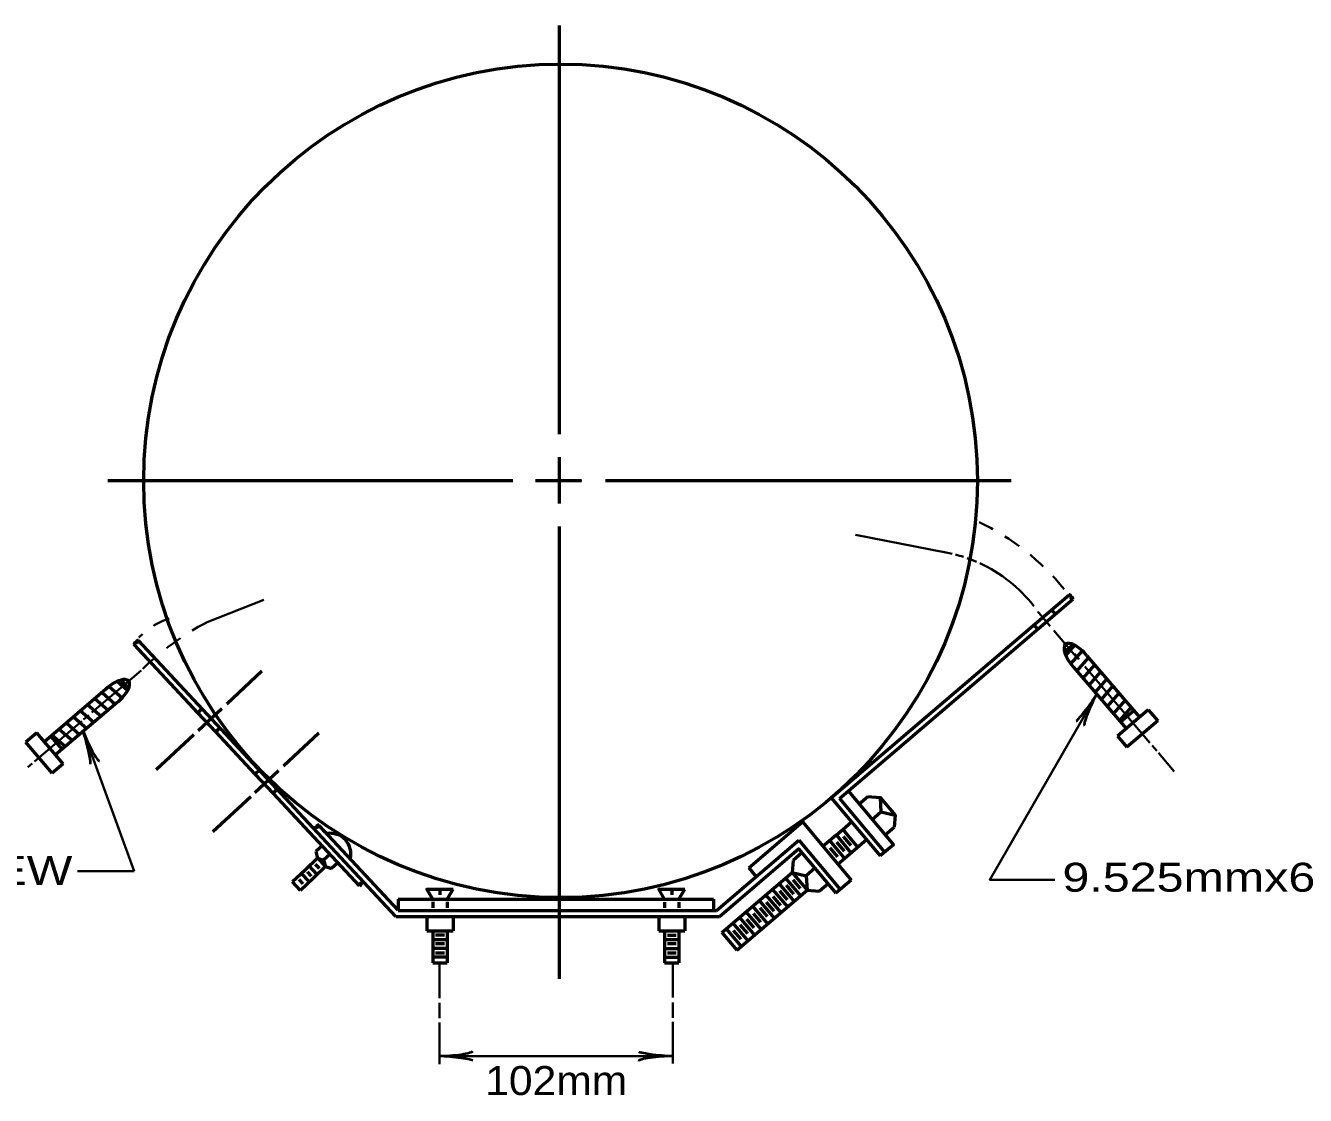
# Model space of a CAD drawing. Extents: x 14808 to 15663, y 10944 to 11488.
# Drawn here: x 15031.3 to 15163.9, y 11082.5 to 11193.4 of the extents above; entities that cross this region are included whole.
import ezdxf

# ---------------------------------------------------------------- set-up
doc = ezdxf.new("R2010")
doc.units = 0
doc.header["$LTSCALE"] = 1.2
doc.linetypes.add('SHORT_DASHED', pattern=[2.7, 1.5, -1.2])
doc.layers.add('1', color=7, linetype='Continuous', lineweight=53)

msp = doc.modelspace()

# ---------------------------------------------------------------- linework, layer by layer
at = {"layer": '1'}
for p, q in [((15086.651, 11151.055), (15086.651, 11193.393)), ((15086.651, 11146.233), (15086.651, 11148.668)), ((15039.851, 11146.233), (15081.805, 11146.233)), ((15084.167, 11146.233), (15088.942, 11146.233)), ((15086.651, 11143.863), (15086.651, 11146.233)), ((15091.416, 11146.233), (15133.451, 11146.233)), ((15114.819, 11113.353), (15139.457, 11134.395)), ((15115.661, 11113.283), (15139.846, 11133.939)), ((15137.632, 11132.837), (15138.021, 11132.38)), ((15135.807, 11131.278), (15136.196, 11130.822)), ((15069.706, 11101.058), (15043.022, 11129.672)), ((15049.193, 11122.175), (15042.594, 11129.251)), ((15138.992, 11128.472), (15139.9, 11129.247)), ((15139.132, 11128.093), (15140.059, 11129.16)), ((15139.65, 11127.226), (15140.834, 11128.588)), ((15139.933, 11126.908), (15145.387, 11120.523)), ((15140.286, 11126.495), (15141.48, 11127.869)), ((15140.917, 11125.757), (15142.111, 11127.131)), ((15141.312, 11128.065), (15146.756, 11121.692)), ((15041.223, 11125.557), (15041.998, 11124.65)), ((15052.168, 11123.103), (15055.819, 11126.506)), ((15141.547, 11125.019), (15142.741, 11126.392)), ((15142.178, 11124.281), (15143.372, 11125.654)), ((15039.659, 11124.616), (15033.274, 11119.162)), ((15039.246, 11124.263), (15040.62, 11123.069)), ((15039.977, 11124.899), (15041.339, 11123.715)), ((15040.844, 11125.418), (15041.911, 11124.49)), ((15142.808, 11123.543), (15144.002, 11124.916)), ((15040.816, 11123.237), (15034.443, 11117.793)), ((15037.77, 11123.002), (15039.144, 11121.808)), ((15038.508, 11123.632), (15039.882, 11122.438)), ((15143.438, 11122.805), (15144.632, 11124.178)), ((15144.069, 11122.067), (15145.263, 11123.44)), ((15036.294, 11121.741), (15037.667, 11120.547)), ((15037.032, 11122.372), (15038.405, 11121.178)), ((15049.621, 11122.595), (15049.193, 11122.175)), ((15051.035, 11120.199), (15049.193, 11122.175)), ((15049.196, 11120.331), (15051.655, 11122.624)), ((15147.668, 11122.471), (15144.474, 11119.744)), ((15144.699, 11121.328), (15145.893, 11122.702)), ((15146.171, 11122.377), (15144.802, 11121.207)), ((15147.668, 11122.471), (15148.642, 11121.331)), ((15034.818, 11120.48), (15036.191, 11119.286)), ((15035.556, 11121.111), (15036.929, 11119.917)), ((15051.463, 11120.62), (15051.035, 11120.199)), ((15148.642, 11121.331), (15145.449, 11118.603)), ((15032.495, 11120.075), (15031.354, 11119.101)), ((15034.082, 11115.907), (15031.354, 11119.101)), ((15035.222, 11116.881), (15032.495, 11120.075)), ((15035.128, 11118.378), (15033.958, 11119.747)), ((15034.079, 11119.85), (15035.453, 11118.656)), ((15044.848, 11116.277), (15048.76, 11119.925)), ((15055.128, 11115.81), (15051.035, 11120.199)), ((15058.06, 11116.666), (15061.711, 11120.07)), ((15144.474, 11119.744), (15145.449, 11118.603)), ((15035.222, 11116.881), (15034.082, 11115.907)), ((15055.088, 11113.895), (15057.546, 11116.187)), ((15055.557, 11116.23), (15055.128, 11115.81)), ((15056.97, 11113.834), (15055.128, 11115.81)), ((15057.399, 11114.255), (15056.97, 11113.835)), ((15065.918, 11104.239), (15056.97, 11113.835)), ((15050.739, 11109.841), (15054.652, 11113.489)), ((15114.819, 11113.353), (15119.878, 11107.325)), ((15115.661, 11113.283), (15120.337, 11107.711)), ((15117.689, 11112.705), (15118.602, 11113.484)), ((15119.878, 11113.391), (15121.437, 11111.566)), ((15119.067, 11111.092), (15119.965, 11111.887)), ((15062.382, 11109.791), (15061.703, 11110.519)), ((15061.707, 11110.515), (15061.707, 11110.515)), ((15069.931, 11101.696), (15061.745, 11110.474)), ((15106.258, 11106.082), (15111.833, 11110.844)), ((15115.316, 11109.494), (15116, 11110.079)), ((15116, 11110.079), (15116.913, 11110.858)), ((15116, 11110.079), (15117.543, 11108.24)), ((15120.417, 11109.511), (15121.329, 11110.291)), ((15062.068, 11108.383), (15061.404, 11107.775)), ((15102.931, 11101.663), (15111.472, 11108.958)), ((15111.472, 11108.958), (15115.749, 11103.861)), ((15113.947, 11108.325), (15115.316, 11109.495)), ((15114.632, 11108.91), (15116.174, 11107.071)), ((15115.316, 11109.495), (15116.859, 11107.656)), ((15115.364, 11108.746), (15116.143, 11107.834)), ((15115.49, 11106.487), (15118.456, 11109.02)), ((15116.048, 11109.331), (15116.827, 11108.418)), ((15061.591, 11107.104), (15060.286, 11105.865)), ((15061.591, 11107.104), (15062.417, 11106.234)), ((15062.879, 11107.499), (15062.215, 11106.891)), ((15111.78, 11107.658), (15110.853, 11106.867)), ((15114.679, 11108.161), (15115.459, 11107.249)), ((15060.286, 11105.865), (15058.98, 11104.626)), ((15060.942, 11105.231), (15060.529, 11105.666)), ((15061.554, 11105.414), (15060.728, 11106.285)), ((15061.769, 11106.024), (15061.37, 11106.443)), ((15063.689, 11106.614), (15063.026, 11106.006)), ((15106.258, 11106.082), (15107.029, 11105.163)), ((15113.13, 11106.049), (15112.217, 11105.27)), ((15115.49, 11106.487), (15116.89, 11104.818)), ((15059.806, 11103.756), (15058.98, 11104.626)), ((15060.098, 11104.438), (15059.669, 11104.89)), ((15060.741, 11104.643), (15059.915, 11105.513)), ((15109.402, 11104.444), (15110.961, 11102.619)), ((15110.087, 11105.028), (15111.645, 11103.203)), ((15110.771, 11105.613), (15112.33, 11103.788)), ((15110.819, 11104.864), (15111.597, 11103.952)), ((15114.48, 11104.44), (15113.581, 11103.673)), ((15116.89, 11104.818), (15115.289, 11103.475)), ((15074.27, 11103.897), (15074.27, 11103.297)), ((15075.02, 11102.858), (15075.62, 11103.897)), ((15098.282, 11103.884), (15098.282, 11103.284)), ((15099.032, 11102.845), (15099.632, 11103.884)), ((15105.03, 11097.553), (15112.33, 11103.788)), ((15108.034, 11103.275), (15109.592, 11101.45)), ((15108.718, 11103.859), (15110.277, 11102.034)), ((15108.765, 11103.111), (15109.544, 11102.199)), ((15109.45, 11103.695), (15110.229, 11102.783)), ((15110.134, 11104.28), (15110.913, 11103.368)), ((15069.92, 11102.858), (15102.62, 11102.858)), ((15069.92, 11102.858), (15069.92, 11101.658)), ((15073.52, 11102.558), (15073.52, 11101.958)), ((15075.02, 11102.558), (15075.02, 11101.958)), ((15097.532, 11102.545), (15097.532, 11101.945)), ((15099.032, 11102.545), (15099.032, 11101.945)), ((15102.62, 11102.858), (15102.62, 11101.658)), ((15106.665, 11102.106), (15108.223, 11100.281)), ((15107.349, 11102.69), (15108.908, 11100.865)), ((15107.397, 11101.942), (15108.176, 11101.03)), ((15108.081, 11102.526), (15108.86, 11101.614)), ((15069.706, 11101.058), (15103.22, 11101.058)), ((15069.92, 11101.658), (15102.92, 11101.658)), ((15072.92, 11101.058), (15072.92, 11099.558)), ((15075.62, 11101.058), (15075.62, 11099.558)), ((15096.932, 11101.045), (15096.932, 11099.545)), ((15099.632, 11101.045), (15099.632, 11099.545)), ((15105.296, 11100.937), (15106.855, 11099.112)), ((15105.98, 11101.521), (15107.539, 11099.696)), ((15106.028, 11100.773), (15106.807, 11099.861)), ((15106.712, 11101.357), (15107.491, 11100.445)), ((15072.92, 11099.558), (15075.62, 11099.558)), ((15073.52, 11099.558), (15073.52, 11096.257)), ((15073.82, 11099.14), (15074.72, 11099.14)), ((15075.02, 11099.558), (15075.02, 11096.257)), ((15096.932, 11099.545), (15099.632, 11099.545)), ((15097.532, 11099.545), (15097.532, 11096.245)), ((15097.832, 11099.128), (15098.732, 11099.128)), ((15099.032, 11099.545), (15099.032, 11096.245)), ((15103.471, 11099.378), (15105.03, 11097.553)), ((15103.927, 11099.768), (15105.486, 11097.943)), ((15103.927, 11099.768), (15105.486, 11097.943)), ((15104.612, 11100.352), (15106.17, 11098.527)), ((15104.659, 11099.604), (15105.438, 11098.692)), ((15105.344, 11100.188), (15106.123, 11099.276)), ((15073.52, 11098.67), (15075.02, 11098.67)), ((15073.52, 11097.754), (15075.02, 11097.754)), ((15073.82, 11098.249), (15074.72, 11098.249)), ((15097.532, 11098.657), (15099.032, 11098.657)), ((15097.532, 11097.741), (15099.032, 11097.741)), ((15097.832, 11098.236), (15098.732, 11098.236)), ((15073.52, 11096.858), (15075.02, 11096.858)), ((15073.82, 11097.283), (15074.72, 11097.283)), ((15097.532, 11096.845), (15099.032, 11096.845)), ((15097.832, 11097.271), (15098.732, 11097.271)), ((15073.52, 11096.257), (15075.02, 11096.257)), ((15097.532, 11096.245), (15099.032, 11096.245))]:
    msp.add_line(p, q, dxfattribs=at)
at = {"layer": '1', "lineweight": 13}
for p, q in [((15088.942, 11146.233), (15088.979, 11146.233)), ((15056.049, 11114.822), (15056.473, 11115.217))]:
    msp.add_line(p, q, dxfattribs=at)
at = {"layer": '1', "lineweight": 35}
for p, q in [((15117.344, 11140.593), (15126.692, 11138.776)), ((15126.396, 11138.833), (15127.356, 11138.647)), ((15056.022, 11133.877), (15050.16, 11131.568)), ((15136.329, 11132.514), (15137.499, 11131.145)), ((15137.884, 11130.693), (15140.382, 11127.769)), ((15140.037, 11128.27), (15140.519, 11127.725)), ((15141.076, 11126.957), (15147.841, 11119.036)), ((15038.199, 11122.185), (15043.31, 11126.55)), ((15037.344, 11121.455), (15037.89, 11121.92)), ((15032.254, 11117.107), (15037.144, 11121.284)), ((15037.304, 11120.246), (15042.58, 11105.753)), ((15148.068, 11118.77), (15148.541, 11118.216)), ((15148.728, 11117.997), (15150.358, 11116.089)), ((15031.558, 11116.513), (15032.022, 11116.909)), ((15036.716, 11105.753), (15042.58, 11105.753)), ((15074.222, 11096.251), (15074.222, 11092.587)), ((15098.383, 11096.3), (15098.383, 11092.637)), ((15074.222, 11092.092), (15074.222, 11090.508)), ((15098.383, 11092.141), (15098.383, 11090.557)), ((15074.222, 11090.062), (15074.222, 11085.751)), ((15098.383, 11090.112), (15098.383, 11085.8)), ((15074.206, 11086.583), (15098.311, 11086.583))]:
    msp.add_line(p, q, dxfattribs=at)
at = {"layer": '1'}
for points in [[(15086.651, 11094.575), (15086.651, 11103.126), (15086.651, 11141.475)], [(15116.574, 11114.062), (15121.257, 11108.482), (15119.878, 11107.325)], [(15118.602, 11113.484), (15119.878, 11113.391), (15119.965, 11111.887), (15121.437, 11111.566), (15121.329, 11110.291)], [(15111.833, 11110.844), (15113.947, 11108.325), (15115.49, 11106.487)], [(15061.404, 11107.775), (15061.591, 11107.104), (15062.215, 11106.891), (15062.417, 11106.234), (15063.026, 11106.006)], [(15103.22, 11101.058), (15111.433, 11108.072), (15115.289, 11103.475)], [(15062.417, 11106.234), (15061.112, 11104.995), (15059.806, 11103.756)], [(15110.853, 11106.867), (15110.771, 11105.613), (15112.217, 11105.27), (15112.33, 11103.788), (15113.581, 11103.673)], [(15103.471, 11099.378), (15110.087, 11105.028), (15110.771, 11105.613)], [(15073.52, 11102.858), (15072.92, 11103.897), (15075.62, 11103.897)], [(15097.532, 11102.845), (15096.932, 11103.884), (15099.632, 11103.884)]]:
    msp.add_lwpolyline(points, dxfattribs=at)
at = {"layer": '1', "lineweight": 35}
msp.add_lwpolyline([(15137.989, 11104.854), (15131.231, 11104.854), (15142.338, 11124.092)], dxfattribs=at)
at = {"layer": '1'}
msp.add_circle((15086.766, 11146.205), 43.2, dxfattribs=at)
at = {"layer": '1', "linetype": 'SHORT_DASHED', "lineweight": 35}
for centre, radius, start, end in [((15118.921, 11118.68), 25.821, 39.09076, 64.25674), ((15048.357, 11125.007), 7.247, 107.18277, 136.93055), ((15062.9, 11106.992), 27.682, 117.40174, 135.04708)]:
    msp.add_arc(centre, radius, start, end, dxfattribs=at)
at = {"layer": '1', "lineweight": 35}
for start, end in [(72.09704, 75.39826), (66.7088, 70.55356), (37.97532, 65.20978), (34.61481, 35.37094)]:
    msp.add_arc((15123.868, 11123.912), 15.141, start, end, dxfattribs=at)
at = {"layer": '1'}
for centre, radius, start, end in [((15139.486, 11134.223), 0.175, 341.35274, 99.6479), ((15139.817, 11134.111), 0.175, 161.35274, 279.6479), ((15139.681, 11133.995), 0.175, 341.35274, 99.6479), ((15042.978, 11129.503), 0.175, 75.35274, 193.6479), ((15042.852, 11129.631), 0.175, 255.35274, 13.6479), ((15042.764, 11129.293), 0.175, 75.35274, 193.6479), ((15140.131, 11128.795), 1.184, 154.26025, 195.83671), ((15142.622, 11129.591), 3.798, 197.13743, 224.94055), ((15139.401, 11128.173), 1.184, 64.26025, 105.83671), ((15137.9, 11125.423), 4.316, 37.7559, 62.16939), ((15042.342, 11121.927), 3.798, 107.13743, 134.94055), ((15041.546, 11124.418), 1.184, 64.26025, 105.83671), ((15038.174, 11126.649), 4.316, 307.7559, 332.16939), ((15040.924, 11125.148), 1.184, 334.26025, 15.83671), ((15061.436, 11110.145), 0.175, 73.35274, 191.6479), ((15061.657, 11110.347), 0.175, 73.35274, 191.6479), ((15061.536, 11110.479), 0.175, 253.35274, 11.6479), ((15061.536, 11110.479), 0.175, 11.56977, 11.63706), ((15062.89, 11107.524), 2.149, 346.12036, 99.8792), ((15066.077, 11104.312), 0.175, 86.35274, 204.6479), ((15065.929, 11104.413), 0.175, 266.35274, 24.6479), ((15066.099, 11104.661), 0.175, 266.35274, 24.6479)]:
    msp.add_arc(centre, radius, start, end, dxfattribs=at)
at = {"layer": '1', "lineweight": 40}
for centre, major_axis, ratio, start_param, end_param in [((15141.446, 11123.055), (-1.236, -1.72), 0.07063, 6.2823074, 8.5597026), ((15141.971, 11122.793), (0.909, 1.949), 0.122415, 0.8963533, 3.1415927), ((15037.526, 11118.896), (0.523, -2.053), 0.07063, 6.2823074, 8.5597026), ((15038.064, 11119.129), (-0.909, 1.95), 0.122415, 0.8963533, 3.1415927), ((15075.516, 11086.915), (-2.143, -0.187), 0.122415, 0.8963533, 3.1415927), ((15075.551, 11086.329), (2.108, -0.211), 0.07063, 6.2823074, 8.5597026), ((15097.002, 11086.251), (2.143, 0.187), 0.122415, 0.8963533, 3.1415927), ((15096.966, 11086.837), (2.108, -0.211), 0.07063, 3.1407148, 5.41811)]:
    msp.add_ellipse(centre, major_axis=major_axis, ratio=ratio, start_param=start_param, end_param=end_param, dxfattribs=at)

# ---------------------------------------------------------------- texts
at = {"layer": '1'}
for s, width, p in [('9.525mmx63.5mm LAG SCREW', 1.25, (14963.168, 11104.329)), ('9.525mmx63.5mm LAG SCREW', 1.25, (15138.771, 11103.619)), ('102mm', 1.1, (15078.958, 11082.545))]:
    msp.add_text(s, height=3, dxfattribs=dict(at, width=width)).set_placement(p)

doc.saveas('drawing.dxf')
